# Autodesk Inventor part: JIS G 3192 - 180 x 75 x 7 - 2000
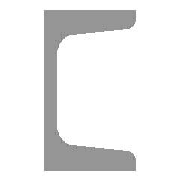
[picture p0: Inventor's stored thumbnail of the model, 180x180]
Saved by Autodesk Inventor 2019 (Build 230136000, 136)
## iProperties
IsCustomPart: 1
Created: 2017-02
Part Number: JIS G 3192 - 180 x 75 x 7 - 2000
Material: 鋼、軟鋼
Description: U 形熱間圧延鋼
Document SubType Name: Modeling
Standard: JIS
Designer: shimont
Standard Revision: 2014
Standards Organization: JIS
Language: ja-JP
Size Designation: 180 x 75 x 7
Categories: <MemberInstance><Categories><Category DisplayName="形鋼" InternalName="089c4875-fa83-4c05-b084-43b9cc11f5ed" Mnemonic="GRDR"><CategoryParameter DisplayName="長さ単位ご
Stock Number: 180 x 75 x 7
Density: 7.85 g/cm^3
Appearance: 半つや出し
Mass: 42699 g
Surface Area: 12516.4 cm^2
Volume: 5439.37 cm^3
_CCFamilyMember: 6
_CCFamilyDisplayName: JIS G 3192 - U 形熱間圧延鋼
_FrameMemberDoc: Frame Member File
_Version: 15.0.0
_GetPNFromCC: 1
G_L: 2000.000 mm
G_W: 75.000 mm
G_H: 180.000 mm
Author: shimont
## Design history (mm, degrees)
node "開始平面"
node "終了平面"
sketch "スケッチ"
  geometry: L1 (-21.3, 0)-(-21.3, 90); L2 (-21.3, 90)-(53.7, 90); L3 (53.7, 90)-(53.7, 87.514); L4 (48.679, 82.035)-(-4.259, 77.404); L5 (-14.3, 66.446)-(-14.3, 0); L6 (-14.3, 0)-(-21.3, 0); L7 (19.7, 90)-(19.7, 79.5); L8 (53.7, 82.475)-(53.7, 79.5); L9 (53.7, 79.5)-(19.7, 79.5); L10 (0, 15)-(0, -27); L11 (-5.539, 0)-(16.007, 0); L12 (-21.3, 0)-(-21.3, -90); L13 (-21.3, -90)-(53.7, -90); L14 (53.7, -90)-(53.7, -87.514); L15 (48.679, -82.035)-(-4.259, -77.404); L16 (-14.3, -66.446)-(-14.3, 0); L17 (0, 126)-(0, -126) reference; L18 (-36.513, 0)-(69.978, 0) reference; A1 r 11 centre (-3.3, 66.446) between (-4.259, 77.404) and (-14.3, 66.446); A2 r 11 centre (-3.3, -66.446) between (-14.3, -66.446) and (-4.259, -77.404); A3 r 5.5 centre (48.2, 87.514) between (48.679, 82.035) and (53.7, 87.514); A4 r 5.5 centre (48.2, -87.514) between (53.7, -87.514) and (48.679, -82.035); 5 further points
  constraints: 32 end point, 12 point on line, 8 point on circle, 8 tangent, 6 symmetric about line, 4 centre point, 4 parallel, 3 collinear, 3 perpendicular, 2 equal radius, 5 other
  dimensions: "d0" = 7 distance between parallel lines of L1 L5 (= G_T); "d1" = 90 distance between parallel lines of L6 L2 (= 0.5 x G_H); "d2" = 75 distance between parallel lines of L3 L1 (= G_W); "d3" = 10.5 distance of L2.end L8.end (= G_T1); "d4" = 34 distance of L7.start L2.end (= G_C); "d5" = 2.97466 distance of L8.start L8.end (computed from G_NG, G_C); "d23" = 11 radius of A1 (= G_IR); "d24" = 5.5 radius of A3 (= G_ER); "d25" = 21.3 distance between parallel lines of L10 L12 (= ey)
extrude "ボディ" new body sketch "スケッチ" stored distance "d6" = 2000 (= G_L); taper "d7" = 0 deg
node "Driven Length"
  sketch "Sketch3"
    geometry: L1 (0, 0)-(10, 0) reference
    constraints: 2 end point, 1 horizontal
  workplane "Work Plane3"
  sketch "Sketch4"
    geometry: L1 (-2, 0)-(12, 0) reference; L2 (-2, 2000)-(12, 2000) reference
    dimensions: "d29" = 2000 distance between parallel lines of L1 L2 (derived)
body "Solid1"
other parameters: "G_W" = 75 [user parameter; used in 1 equation term], "G_H" = 180 [user parameter; used in 1 equation term], "G_T" = 7 [user parameter; used in 1 equation term], "G_T1" = 10.5 [user parameter; used in 1 equation term], "G_NG" = 0.8749 [user parameter; used in 1 equation term], "G_ER" = 5.5 [user parameter; used in 1 equation term], "G_IR" = 11 [user parameter; used in 1 equation term], "G_C" = 34 [user parameter; used in 2 equation terms], "G_L" = 2000 (= d29) [user parameter; used in 1 equation term], "ey" = 21.3 [user parameter; used in 1 equation term], "G_OFFSET_START" = 0 [user parameter; used in 1 equation term], "G_OFFSET_END" = 0 [user parameter; used in 1 equation term], "d26" = 0 (computed from G_OFFSET_START), "d28" = 90 deg
